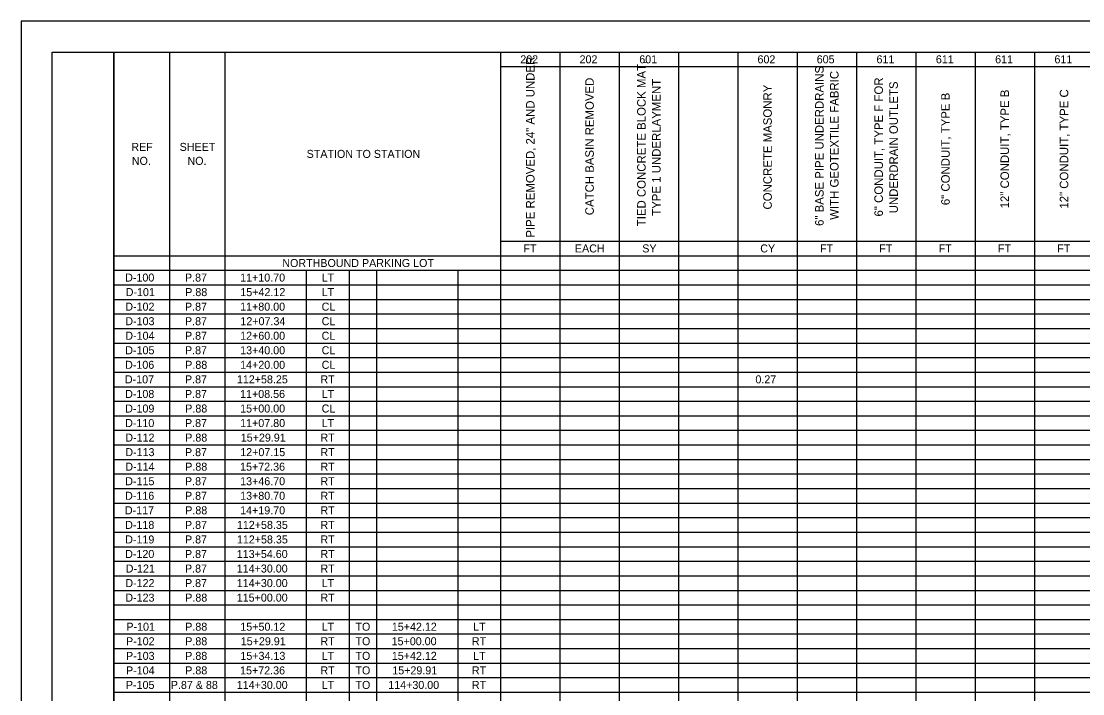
# Model space of a CAD drawing. Extents: x 0 to 34, y 0 to 22.
# Drawn here: x 0 to 17.22, y 11.09 to 22 of the extents above; entities that cross this region are included whole.
import ezdxf

# ---------------------------------------------------------------- set-up
doc = ezdxf.new("R2010")
doc.units = 0
for name, color, linetype in [('SH_Border', 7, 'Continuous'), ('SH_Cut_Line', 7, 'Continuous'), ('SH_Text', 7, 'Continuous')]:
    doc.layers.add(name, color=color, linetype=linetype)

msp = doc.modelspace()

# ---------------------------------------------------------------- linework, layer by layer
at = {"layer": 'SH_Border'}
for points in [[(0.5, 21.5), (1.5, 21.5), (1.5, 0.5), (0.5, 0.5)], [(1.5, 21.5), (33.5, 21.5), (33.5, 0.5), (1.5, 0.5)]]:
    msp.add_lwpolyline(points, close=True, dxfattribs=at)
at = {"layer": 'SH_Cut_Line'}
msp.add_lwpolyline([(0, 0), (34, 0), (34, 22), (0, 22)], close=True, dxfattribs=at)
at = {"layer": 'SH_Text'}
for p, q in [((1.5, 21.5), (32, 21.5)), ((1.5, 21.5), (1.5, 18.194)), ((2.403, 21.5), (2.403, 0.736)), ((3.306, 21.5), (3.306, 0.736)), ((7.778, 21.5), (7.778, 0.5)), ((8.74, 21.5), (8.74, 0.5)), ((9.702, 21.5), (9.702, 0.5)), ((10.665, 21.5), (10.665, 0.5)), ((11.627, 21.5), (11.627, 0.5)), ((12.59, 21.5), (12.59, 0.5)), ((13.552, 21.5), (13.552, 0.5)), ((14.514, 21.5), (14.514, 0.5)), ((15.477, 21.5), (15.477, 0.5)), ((16.439, 21.5), (16.439, 0.5)), ((7.778, 21.264), (32, 21.264)), ((7.778, 18.431), (32, 18.431)), ((1.5, 18.194), (32, 18.194)), ((1.5, 18.194), (1.5, 0.736)), ((1.5, 17.958), (32, 17.958)), ((4.624, 17.958), (4.624, 0.736)), ((5.32, 17.958), (5.32, 0.736)), ((5.764, 17.958), (5.764, 0.736)), ((7.082, 17.958), (7.082, 0.736)), ((1.5, 17.722), (32, 17.722)), ((1.5, 17.486), (32, 17.486)), ((1.5, 17.25), (32, 17.25)), ((1.5, 17.014), (32, 17.014)), ((1.5, 16.778), (32, 16.778)), ((1.5, 16.542), (32, 16.542)), ((1.5, 16.306), (32, 16.306)), ((1.5, 16.069), (32, 16.069)), ((1.5, 15.833), (32, 15.833)), ((1.5, 15.597), (32, 15.597)), ((1.5, 15.361), (32, 15.361)), ((1.5, 15.125), (32, 15.125)), ((1.5, 14.889), (32, 14.889)), ((1.5, 14.653), (32, 14.653)), ((1.5, 14.417), (32, 14.417)), ((1.5, 14.181), (32, 14.181)), ((1.5, 13.944), (32, 13.944)), ((1.5, 13.708), (32, 13.708)), ((1.5, 13.472), (32, 13.472)), ((1.5, 13.236), (32, 13.236)), ((1.5, 13), (32, 13)), ((1.5, 12.764), (32, 12.764)), ((1.5, 12.528), (32, 12.528)), ((1.5, 12.292), (32, 12.292)), ((1.5, 12.056), (32, 12.056)), ((1.5, 11.819), (32, 11.819)), ((1.5, 11.583), (32, 11.583)), ((1.5, 11.347), (32, 11.347)), ((1.5, 11.111), (32, 11.111))]:
    msp.add_line(p, q, dxfattribs=at)

# ---------------------------------------------------------------- texts
for s, height, p in [('202', 0.1299, (8.097, 21.317)), ('202', 0.1299, (9.059, 21.317)), ('601', 0.1299, (10.028, 21.317)), ('602', 0.1299, (11.946, 21.317)), ('605', 0.1299, (12.907, 21.317)), ('611', 0.1299, (13.877, 21.317)), ('611', 0.1299, (14.84, 21.317)), ('611', 0.1299, (15.802, 21.317)), ('611', 0.1299, (16.764, 21.317)), ('REF', 0.1299, (1.786, 19.896)), ('SHEET', 0.1299, (2.57, 19.896)), ('STATION TO STATION', 0.12986, (4.631, 19.782)), ('NO.', 0.1299, (1.794, 19.669)), ('NO.', 0.1299, (2.697, 19.669)), ('FT', 0.1299, (8.148, 18.248)), ('EACH', 0.1299, (8.984, 18.248)), ('SY', 0.1299, (10.076, 18.248)), ('CY', 0.1299, (11.991, 18.248)), ('FT', 0.1299, (12.96, 18.248)), ('FT', 0.1299, (13.922, 18.248)), ('FT', 0.1299, (14.885, 18.248)), ('FT', 0.1299, (15.847, 18.248)), ('FT', 0.1299, (16.809, 18.248)), ('NORTHBOUND PARKING LOT', 0.12986, (4.236, 18.011)), ('D-100', 0.1299, (1.686, 17.775)), ('P.87', 0.1299, (2.657, 17.775)), ('11+10.70', 0.1299, (3.552, 17.775)), ('LT', 0.1299, (4.874, 17.775)), ('D-101', 0.1299, (1.695, 17.539)), ('P.88', 0.1299, (2.661, 17.539)), ('15+42.12', 0.1299, (3.555, 17.539)), ('LT', 0.1299, (4.874, 17.539)), ('D-102', 0.1299, (1.689, 17.303)), ('P.87', 0.1299, (2.657, 17.303)), ('11+80.00', 0.1299, (3.552, 17.303)), ('CL', 0.1299, (4.874, 17.303)), ('D-103', 0.1299, (1.689, 17.067)), ('P.87', 0.1299, (2.657, 17.067)), ('12+07.34', 0.1299, (3.556, 17.067)), ('CL', 0.1299, (4.874, 17.067)), ('D-104', 0.1299, (1.689, 16.831)), ('P.87', 0.1299, (2.657, 16.831)), ('12+60.00', 0.1299, (3.552, 16.831)), ('CL', 0.1299, (4.874, 16.831)), ('D-105', 0.1299, (1.688, 16.595)), ('P.87', 0.1299, (2.657, 16.595)), ('13+40.00', 0.1299, (3.552, 16.595)), ('CL', 0.1299, (4.874, 16.595)), ('D-106', 0.1299, (1.685, 16.359)), ('P.88', 0.1299, (2.661, 16.359)), ('14+20.00', 0.1299, (3.552, 16.359)), ('CL', 0.1299, (4.874, 16.359)), ('D-107', 0.1299, (1.682, 16.123)), ('P.87', 0.1299, (2.657, 16.123)), ('112+58.25', 0.1299, (3.499, 16.123)), ('RT', 0.1299, (4.855, 16.123)), ('0.27', 0.1299, (11.912, 16.123)), ('D-108', 0.1299, (1.686, 15.886)), ('P.87', 0.1299, (2.657, 15.886)), ('11+08.56', 0.1299, (3.551, 15.886)), ('LT', 0.1299, (4.874, 15.886)), ('D-109', 0.1299, (1.687, 15.65)), ('P.88', 0.1299, (2.661, 15.65)), ('15+00.00', 0.1299, (3.552, 15.65)), ('CL', 0.1299, (4.874, 15.65)), ('D-110', 0.1299, (1.686, 15.414)), ('P.87', 0.1299, (2.657, 15.414)), ('11+07.80', 0.1299, (3.552, 15.414)), ('LT', 0.1299, (4.874, 15.414)), ('D-112', 0.1299, (1.689, 15.178)), ('P.88', 0.1299, (2.661, 15.178)), ('15+29.91', 0.1299, (3.562, 15.178)), ('RT', 0.1299, (4.855, 15.178)), ('D-113', 0.1299, (1.689, 14.942)), ('P.87', 0.1299, (2.657, 14.942)), ('12+07.15', 0.1299, (3.554, 14.942)), ('RT', 0.1299, (4.855, 14.942)), ('D-114', 0.1299, (1.689, 14.706)), ('P.88', 0.1299, (2.661, 14.706)), ('15+72.36', 0.1299, (3.551, 14.706)), ('RT', 0.1299, (4.855, 14.706)), ('D-115', 0.1299, (1.688, 14.47)), ('P.87', 0.1299, (2.657, 14.47)), ('13+46.70', 0.1299, (3.552, 14.47)), ('RT', 0.1299, (4.855, 14.47)), ('D-116', 0.1299, (1.685, 14.234)), ('P.87', 0.1299, (2.657, 14.234)), ('13+80.70', 0.1299, (3.552, 14.234)), ('RT', 0.1299, (4.855, 14.234)), ('D-117', 0.1299, (1.682, 13.998)), ('P.88', 0.1299, (2.661, 13.998)), ('14+19.70', 0.1299, (3.552, 13.998)), ('RT', 0.1299, (4.855, 13.998)), ('D-118', 0.1299, (1.686, 13.761)), ('P.87', 0.1299, (2.657, 13.761)), ('112+58.35', 0.1299, (3.499, 13.761)), ('RT', 0.1299, (4.855, 13.761)), ('D-119', 0.1299, (1.687, 13.525)), ('P.87', 0.1299, (2.657, 13.525)), ('112+58.35', 0.1299, (3.499, 13.525)), ('RT', 0.1299, (4.855, 13.525)), ('D-120', 0.1299, (1.686, 13.289)), ('P.87', 0.1299, (2.657, 13.289)), ('113+54.60', 0.1299, (3.497, 13.289)), ('RT', 0.1299, (4.855, 13.289)), ('D-121', 0.1299, (1.695, 13.053)), ('P.87', 0.1299, (2.657, 13.053)), ('114+30.00', 0.1299, (3.497, 13.053)), ('RT', 0.1299, (4.855, 13.053)), ('D-122', 0.1299, (1.689, 12.817)), ('P.87', 0.1299, (2.657, 12.817)), ('114+30.00', 0.1299, (3.497, 12.817)), ('LT', 0.1299, (4.874, 12.817)), ('D-123', 0.1299, (1.689, 12.581)), ('P.88', 0.1299, (2.661, 12.581)), ('115+00.00', 0.1299, (3.497, 12.581)), ('RT', 0.1299, (4.855, 12.581)), ('P-101', 0.1299, (1.706, 12.109)), ('P.88', 0.1299, (2.661, 12.109)), ('15+50.12', 0.1299, (3.555, 12.109)), ('LT', 0.1299, (4.874, 12.109)), ('TO', 0.1299, (5.423, 12.109)), ('15+42.12', 0.1299, (6.013, 12.109)), ('LT', 0.1299, (7.332, 12.109)), ('P-102', 0.1299, (1.7, 11.873)), ('P.88', 0.1299, (2.661, 11.873)), ('15+29.91', 0.1299, (3.562, 11.873)), ('RT', 0.1299, (4.855, 11.873)), ('TO', 0.1299, (5.423, 11.873)), ('15+00.00', 0.1299, (6.01, 11.873)), ('RT', 0.1299, (7.312, 11.873)), ('P-103', 0.1299, (1.7, 11.636)), ('P.88', 0.1299, (2.661, 11.636)), ('15+34.13', 0.1299, (3.556, 11.636)), ('LT', 0.1299, (4.874, 11.636)), ('TO', 0.1299, (5.423, 11.636)), ('15+42.12', 0.1299, (6.013, 11.636)), ('LT', 0.1299, (7.332, 11.636)), ('P-104', 0.1299, (1.7, 11.4)), ('P.88', 0.1299, (2.661, 11.4)), ('15+72.36', 0.1299, (3.551, 11.4)), ('RT', 0.1299, (4.855, 11.4)), ('TO', 0.1299, (5.423, 11.4)), ('15+29.91', 0.1299, (6.02, 11.4)), ('RT', 0.1299, (7.312, 11.4)), ('P-105', 0.1299, (1.698, 11.164)), ('P.87 & 88', 0.1299, (2.427, 11.164)), ('114+30.00', 0.1299, (3.497, 11.164)), ('LT', 0.1299, (4.874, 11.164)), ('TO', 0.1299, (5.423, 11.164)), ('114+30.00', 0.1299, (5.955, 11.164)), ('RT', 0.1299, (7.312, 11.164))]:
    msp.add_text(s, height=height, dxfattribs=at).set_placement(p)
for s, p in [('PIPE REMOVED, 24" AND UNDER', (8.328, 18.488)), ('TIED CONCRETE BLOCK MAT, ', (10.132, 18.673)), ('6" BASE PIPE UNDERDRAINS ', (13.019, 18.678)), ('WITH GEOTEXTILE FABRIC', (13.261, 18.777)), ('CATCH BASIN REMOVED', (9.29, 18.852)), ('TYPE 1 UNDERLAYMENT', (10.374, 18.843)), ('6" CONDUIT, TYPE F FOR ', (13.981, 18.831)), ('UNDERDRAIN OUTLETS', (14.223, 18.883)), ('CONCRETE MASONRY', (12.178, 18.944)), ('12" CONDUIT, TYPE B', (16.027, 18.963)), ('12" CONDUIT, TYPE C', (16.989, 18.958)), ('6" CONDUIT, TYPE B', (15.065, 19.015))]:
    msp.add_text(s, height=0.13843, rotation=90, dxfattribs=at).set_placement(p)

doc.saveas('drawing.dxf')
